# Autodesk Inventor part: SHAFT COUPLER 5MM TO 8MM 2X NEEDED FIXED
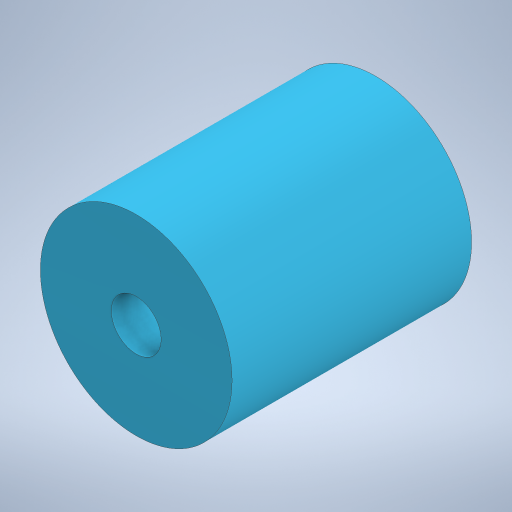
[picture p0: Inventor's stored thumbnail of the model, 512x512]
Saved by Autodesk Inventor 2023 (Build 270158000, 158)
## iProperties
Created: 2025-07
Part Number: SHAFT COUPLER 5MM TO 8MM 2X NEEDED FIXED
Material: Generic
Document SubType Name: Modeling
Designer: erjon
Density: 1 g/cm^3
Appearance: Default
Author: erjon
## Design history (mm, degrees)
feature "Base1"
sketch "Sketch1"
  geometry: L1 (0, 10)-(0, -7); L2 (0, -7)-(9.883, -7); L3 (0, -7)-(-13.157, -7); C1 r 10 at (0, 0) reference; C2 r 4 at (0, 0) reference; 4 further points
  constraints: 6 end point, 1 horizontal, 1 perpendicular, 1 vertical, 1 vertical alignment, 1 other
  dimensions: "d0" = 17 distance of L1.start L1.end
extrude "Extrusion1" cut sketch "Sketch1" distance "d1" = 25; taper "d2" = 0 deg
sketch "Sketch2"
  geometry: C1 r 2.6 at (0, 0); 1 further point
  constraints: 1 centre point, 1 coincident
  dimensions: "d3" = 5.2 diameter of C1
extrude "Extrusion2" cut sketch "Sketch2" distance "d5" = 25; taper "d6" = 0 deg
sketch "Sketch3"
  geometry: L1 (0, 2.6)-(0, -2.1); L2 (0, -2.1)-(-4.697, -2.1); L3 (-4.697, -2.1)-(5.457, -2.1); 5 further points
  constraints: 6 end point, 1 perpendicular, 1 point on line, 1 vertical, 2 other
  dimensions: "d7" = 4.7 distance of L1.start L1.end
extrude "Extrusion3" join sketch "Sketch3" distance "d8" = 12.5; taper "d9" = 0 deg
sketch "Sketch5"
  geometry: C1 r 2.6 at (0, 0); 1 further point
  constraints: 1 centre point, 1 coincident
extrude "Extrusion4" cut sketch "Sketch5" distance "d10" = 4; taper "d11" = 0 deg
sketch "Sketch6"
  geometry: L1 (17.141, 25)-(-2.859, 25) reference; L2 (7.141, 0)-(7.141, 25); L3 (9.741, 12.5)-(4.541, 12.5) reference; L4 (7.141, 12.5)-(7.141, 0); L5 (7.141, 6.25)-(5.947, 6.25); L6 (7.141, 12.5)-(7.141, 25); L7 (7.141, 18.75)-(5.608, 18.75); C1 r 2.3 at (7.141, 18.75); C2 r 2.3 at (7.141, 6.25); 4 further points
  constraints: 10 end point, 4 midpoint, 2 centre point, 2 coincident, 2 horizontal, 1 collinear, 1 perpendicular
  dimensions: "d13" = 4.6 diameter of C1; "d14" = 4.6 diameter of C2
extrude "Extrusion5" cut sketch "Sketch6" distance "d15" = 8; taper "d16" = 0 deg
sketch "Sketch7"
  geometry: L1 (-7.141, -7)-(7.141, -7) reference; C1 r 2.6 at (0, 0) reference; C2 r 10 at (0, 0); A1 r 10 centre (0, 0) between (7.141, -7) and (-7.141, -7) reference; 3 further points
  constraints: 1 centre point, 1 coincident, 1 concentric
extrude "Extrusion6" join sketch "Sketch7" distance "d17" = 25; taper "d18" = 0 deg
sketch "Sketch8" dims "d24" = 4.6 (derived)
  geometry: C1 r 2.3 at (0, 0); C2 r 1.75 at (0, -12.5); C3 r 1.75 at (0, 0); A1 r 2.3 centre (0, -12.5) between (1.533, -10.785) and (-1.533, -10.785) reference; A2 r 2.3 centre (0, -12.5) between (0.477, -14.75) and (1.533, -14.215) reference; A3 r 2.3 centre (0, -12.5) between (-1.533, -14.215) and (-0.477, -14.75) reference; 5 further points
  constraints: 3 centre point, 3 coincident, 2 horizontal alignment, 2 vertical alignment, 1 other
  dimensions: "d23" = 3.5 diameter of C2; "d25" = 3.5 diameter of C3
extrude "Extrusion7" cut sketch "Sketch8" distance "d19" = 25; taper "d20" = 0 deg
sketch "Sketch9"
  geometry: C1 r 2.6 at (0, 0); 1 further point
  constraints: 1 centre point, 1 coincident
extrude "Extrusion8" cut sketch "Sketch9" distance "d21" = 4.5; taper "d22" = 0 deg
extrude "Extrusion9" join sketch "Sketch8" distance "d26" = 10; taper "d27" = 0 deg
sketch "Sketch10"
  geometry: C1 r 2.6 at (0, 0) reference; C2 r 10 at (0, 0) reference; C3 r 19.922 at (0, 0); 1 further point
  constraints: 1 centre point, 1 coincident
extrude "Extrusion10" cut sketch "Sketch10" distance "d28" = 100; taper "d29" = 0 deg
body "Solid1"
node "Projected Loop1"
node "Projected Loop2"
node "Projected Loop3"
